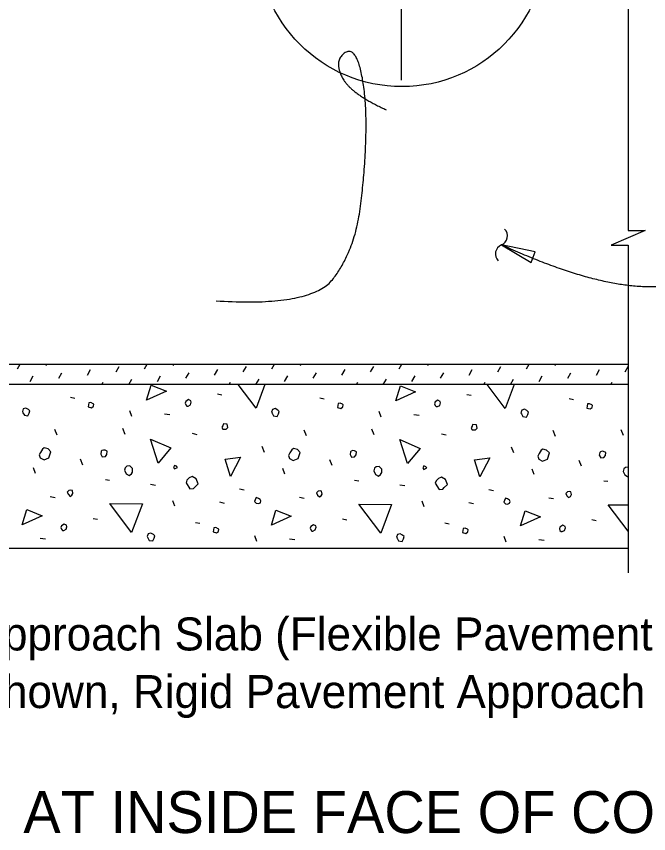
# Model space of a CAD drawing. Extents: x 110341.7 to 110413.5, y 110387.3 to 110417.8.
# Drawn here: x 110353.225 to 110357.09, y 110400.976 to 110405.967 of the extents above; entities that cross this region are included whole.
import ezdxf

# ---------------------------------------------------------------- set-up
doc = ezdxf.new("R2010")
doc.units = 0
for name, color, linetype in [('Border', 7, 'Continuous'), ('CL_Major', 7, 'Continuous'), ('Patterning', 7, 'Continuous'), ('PlotBorder_dp', 7, 'Continuous'), ('SheetBorder_dp', 7, 'Continuous')]:
    doc.layers.add(name, color=color, linetype=linetype)

msp = doc.modelspace()

# ---------------------------------------------------------------- linework, layer by layer
at = {"layer": 'Border'}
msp.add_lwpolyline([(110356.9647, 110406.5102), (110356.9647, 110404.6594), (110357.0681, 110404.6594), (110356.9647, 110404.6144), (110356.8614, 110404.5694), (110356.9647, 110404.5694), (110356.9647, 110402.5685)], dxfattribs=at)
msp.add_lwpolyline([(110356.1898, 110404.5723), (110356.3707, 110404.4632), (110356.3966, 110404.5289)], close=True, dxfattribs=at)
msp.add_circle((110355.5816, 110406.4215), 0.8833, dxfattribs=at)
for centre, start, end in [((110356.1667, 110404.6266), 292.7091, 44.4364), ((110356.2127, 110404.5166), 112.7091, 224.4364)]:
    msp.add_arc(centre, 0.0596, start, end, dxfattribs=at)
for points in [[(110354.4452, 110404.2301), (110355.0337, 110404.1926), (110355.2924, 110404.5405), (110355.3591, 110405.037), (110355.3654, 110405.4921), (110355.2924, 110405.7892), (110355.1649, 110405.6942), (110355.2675, 110405.4951), (110355.4853, 110405.3971)], [(110357.6069, 110404.3154), (110357.447, 110404.3154), (110356.7476, 110404.3154), (110356.1899, 110404.5723)]]:
    msp.add_open_spline(points, degree=2, dxfattribs=at)
at = {"layer": 'CL_Major'}
msp.add_line((110355.5778, 110414.9959), (110355.5778, 110405.5769), dxfattribs=at)
at = {"layer": 'Patterning'}
for p, q in [((110353.231, 110403.8158), (110353.2471, 110403.8435)), ((110353.406, 110403.8352), (110353.4109, 110403.8435)), ((110353.8338, 110403.7963), (110353.8533, 110403.8299)), ((110354.0089, 110403.8158), (110354.0249, 110403.8435)), ((110354.1839, 110403.8352), (110354.1887, 110403.8435)), ((110354.6117, 110403.7963), (110354.6311, 110403.8299)), ((110354.7867, 110403.8158), (110354.8027, 110403.8435)), ((110354.9617, 110403.8352), (110354.9665, 110403.8435)), ((110355.3895, 110403.7963), (110355.4089, 110403.8299)), ((110355.5645, 110403.8158), (110355.5806, 110403.8435)), ((110355.7395, 110403.8352), (110355.7443, 110403.8435)), ((110356.1673, 110403.7963), (110356.1867, 110403.8299)), ((110356.3423, 110403.8158), (110356.3584, 110403.8435)), ((110356.5173, 110403.8352), (110356.5221, 110403.8435)), ((110356.9451, 110403.7963), (110356.9646, 110403.8299)), ((110353.3088, 110403.738), (110353.3283, 110403.7716)), ((110353.4838, 110403.7574), (110353.5033, 110403.791)), ((110353.6588, 110403.7769), (110353.6783, 110403.8105)), ((110354.0866, 110403.738), (110354.1061, 110403.7716)), ((110354.2616, 110403.7574), (110354.2811, 110403.791)), ((110354.4367, 110403.7769), (110354.4561, 110403.8105)), ((110354.8645, 110403.738), (110354.8839, 110403.7716)), ((110355.0395, 110403.7574), (110355.0589, 110403.791)), ((110355.2145, 110403.7769), (110355.2339, 110403.8105)), ((110355.6423, 110403.738), (110355.6617, 110403.7716)), ((110355.8173, 110403.7574), (110355.8367, 110403.791)), ((110355.9923, 110403.7769), (110356.0117, 110403.8105)), ((110356.4201, 110403.738), (110356.4395, 110403.7716)), ((110356.5951, 110403.7574), (110356.6145, 110403.791)), ((110356.7701, 110403.7769), (110356.7896, 110403.8105)), ((110353.7479, 110403.7185), (110353.7561, 110403.7327)), ((110353.9116, 110403.7185), (110353.9311, 110403.7521)), ((110354.5257, 110403.7185), (110354.5339, 110403.7327)), ((110354.6894, 110403.7185), (110354.7089, 110403.7521)), ((110355.3035, 110403.7185), (110355.3117, 110403.7327)), ((110355.4673, 110403.7185), (110355.4867, 110403.7521)), ((110356.0813, 110403.7185), (110356.0895, 110403.7327)), ((110356.2451, 110403.7185), (110356.2645, 110403.7521)), ((110356.8591, 110403.7185), (110356.8673, 110403.7327)), ((110353.5565, 110403.6408), (110353.583, 110403.6355)), ((110354.4545, 110403.662), (110354.481, 110403.6567)), ((110355.0803, 110403.6372), (110355.1068, 110403.6319)), ((110355.9783, 110403.6584), (110356.0049, 110403.6531)), ((110356.6041, 110403.6337), (110356.6306, 110403.6284)), ((110353.9313, 110403.5241), (110353.9189, 110403.5577)), ((110354.131, 110403.54), (110354.1628, 110403.5365)), ((110355.4551, 110403.5206), (110355.4427, 110403.5541)), ((110355.6548, 110403.5365), (110355.6867, 110403.5329)), ((110353.4734, 110403.4092), (110353.4593, 110403.4445)), ((110353.8888, 110403.4145), (110353.8747, 110403.4498)), ((110354.299, 110403.4216), (110354.3272, 110403.4145)), ((110354.9972, 110403.4057), (110354.9831, 110403.441)), ((110355.4127, 110403.411), (110355.3985, 110403.4463)), ((110355.8228, 110403.418), (110355.8511, 110403.411)), ((110356.521, 110403.4021), (110356.5069, 110403.4375)), ((110356.9365, 110403.4074), (110356.9223, 110403.4428)), ((110354.7409, 110403.3049), (110354.7268, 110403.3402)), ((110356.2647, 110403.3014), (110356.2506, 110403.3367)), ((110353.6307, 110403.2271), (110353.6166, 110403.2625)), ((110355.1546, 110403.2236), (110355.1404, 110403.2589)), ((110356.6784, 110403.22), (110356.6642, 110403.2554)), ((110353.3426, 110403.1758), (110353.3302, 110403.2094)), ((110354.8664, 110403.1723), (110354.854, 110403.2059)), ((110356.3902, 110403.1688), (110356.3779, 110403.2024)), ((110353.7686, 110403.1387), (110353.7934, 110403.1352)), ((110355.2924, 110403.1352), (110355.3172, 110403.1317)), ((110356.8163, 110403.1317), (110356.841, 110403.1281)), ((110354.0444, 110403.1104), (110354.0745, 110403.1051)), ((110354.5889, 110403.0822), (110354.6172, 110403.0751)), ((110355.5682, 110403.1069), (110355.5983, 110403.1016)), ((110356.1127, 110403.0786), (110356.141, 110403.0715)), ((110353.431, 110403.0344), (110353.461, 110403.0291)), ((110354.9548, 110403.0309), (110354.9849, 110403.0256)), ((110356.4786, 110403.0274), (110356.5087, 110403.022)), ((110354.1929, 110402.9761), (110354.1805, 110403.0097)), ((110354.4669, 110403.0026), (110354.4952, 110402.9955)), ((110355.7167, 110402.9726), (110355.7043, 110403.0061)), ((110355.9907, 110402.9991), (110356.019, 110402.992)), ((110353.6944, 110402.9018), (110353.7209, 110402.8965)), ((110354.3202, 110402.8771), (110354.3467, 110402.8718)), ((110355.2182, 110402.8983), (110355.2447, 110402.893)), ((110355.844, 110402.8736), (110355.8705, 110402.8683)), ((110356.742, 110402.8948), (110356.7685, 110402.8895)), ((110353.3709, 110402.7799), (110353.4027, 110402.7763)), ((110354.6949, 110402.7604), (110354.6826, 110402.794)), ((110354.8947, 110402.7763), (110354.9265, 110402.7728)), ((110356.2188, 110402.7569), (110356.2064, 110402.7905)), ((110356.4185, 110402.7728), (110356.4503, 110402.7693))]:
    msp.add_line(p, q, dxfattribs=at)
for points in [[(110354.6896, 110403.5754), (110354.5808, 110403.7185)], [(110354.7432, 110403.7185), (110354.6896, 110403.5754)], [(110356.2135, 110403.5718), (110356.1019, 110403.7185)], [(110356.2683, 110403.7185), (110356.2135, 110403.5718)], [(110354.0197, 110403.6231), (110354.0479, 110403.715), (110354.1416, 110403.6779), (110354.0197, 110403.6231)], [(110355.5435, 110403.6196), (110355.5718, 110403.7115), (110355.6654, 110403.6744), (110355.5435, 110403.6196)], [(110354.2671, 110403.5877), (110354.2742, 110403.5877), (110354.2884, 110403.5948), (110354.2937, 110403.6107), (110354.2919, 110403.6196), (110354.2778, 110403.6266), (110354.2601, 110403.616), (110354.2565, 110403.6054), (110354.2601, 110403.5948), (110354.2671, 110403.5877)], [(110355.791, 110403.5842), (110355.798, 110403.5842), (110355.8122, 110403.5913), (110355.8175, 110403.6072), (110355.8157, 110403.616), (110355.8016, 110403.6231), (110355.7839, 110403.6125), (110355.7804, 110403.6019), (110355.7839, 110403.5913), (110355.791, 110403.5842)], [(110353.2648, 110403.5471), (110353.2737, 110403.5312), (110353.2949, 110403.5276), (110353.3037, 110403.5435), (110353.3072, 110403.5577), (110353.2984, 110403.5665), (110353.2825, 110403.5754), (110353.2666, 110403.5701), (110353.2613, 110403.5541), (110353.2648, 110403.5471)], [(110353.6643, 110403.5824), (110353.6838, 110403.5771), (110353.6962, 110403.586), (110353.6979, 110403.5983), (110353.6944, 110403.6019), (110353.6802, 110403.6089), (110353.6679, 110403.6072), (110353.6661, 110403.5948), (110353.6643, 110403.5824)], [(110354.7886, 110403.5435), (110354.7975, 110403.5276), (110354.8187, 110403.5241), (110354.8275, 110403.54), (110354.8311, 110403.5541), (110354.8222, 110403.563), (110354.8063, 110403.5718), (110354.7904, 110403.5665), (110354.7851, 110403.5506), (110354.7886, 110403.5435)], [(110355.1882, 110403.5789), (110355.2076, 110403.5736), (110355.22, 110403.5824), (110355.2217, 110403.5948), (110355.2182, 110403.5983), (110355.2041, 110403.6054), (110355.1917, 110403.6036), (110355.1899, 110403.5913), (110355.1882, 110403.5789)], [(110356.3124, 110403.54), (110356.3213, 110403.5241), (110356.3425, 110403.5206), (110356.3513, 110403.5365), (110356.3549, 110403.5506), (110356.346, 110403.5594), (110356.3301, 110403.5683), (110356.3142, 110403.563), (110356.3089, 110403.5471), (110356.3124, 110403.54)], [(110356.712, 110403.5754), (110356.7314, 110403.5701), (110356.7438, 110403.5789), (110356.7456, 110403.5913), (110356.742, 110403.5948), (110356.7279, 110403.6019), (110356.7155, 110403.6001), (110356.7137, 110403.5877), (110356.712, 110403.5754)], [(110354.4863, 110403.4463), (110354.5076, 110403.4463), (110354.5182, 110403.4569), (110354.5129, 110403.4764), (110354.4899, 110403.4781), (110354.4863, 110403.4675), (110354.481, 110403.4587), (110354.4863, 110403.4463), (110354.4828, 110403.4498)], [(110356.0102, 110403.4428), (110356.0314, 110403.4428), (110356.042, 110403.4534), (110356.0367, 110403.4728), (110356.0137, 110403.4746), (110356.0102, 110403.464), (110356.0049, 110403.4552), (110356.0102, 110403.4428), (110356.0066, 110403.4463)], [(110354.0921, 110403.2395), (110354.0444, 110403.3862), (110354.1699, 110403.3314), (110354.0921, 110403.2395)], [(110355.6159, 110403.2359), (110355.5682, 110403.3827), (110355.6937, 110403.3279), (110355.6159, 110403.2359)], [(110353.3709, 110403.2713), (110353.3939, 110403.2589), (110353.4239, 110403.2713), (110353.4363, 110403.3084), (110353.4186, 110403.3261), (110353.3956, 110403.3314), (110353.385, 110403.3243), (110353.3727, 110403.3049), (110353.3638, 110403.289), (110353.3709, 110403.2713)], [(110353.7403, 110403.2943), (110353.7492, 110403.2784), (110353.7686, 110403.2801), (110353.7775, 110403.2925), (110353.7792, 110403.312), (110353.7669, 110403.3173), (110353.758, 110403.319), (110353.7474, 110403.3155), (110353.7439, 110403.312), (110353.7403, 110403.2943)], [(110354.8947, 110403.2678), (110354.9177, 110403.2554), (110354.9477, 110403.2678), (110354.9601, 110403.3049), (110354.9424, 110403.3226), (110354.9194, 110403.3279), (110354.9088, 110403.3208), (110354.8965, 110403.3014), (110354.8876, 110403.2854), (110354.8947, 110403.2678)], [(110356.4185, 110403.2642), (110356.4415, 110403.2519), (110356.4715, 110403.2642), (110356.4839, 110403.3014), (110356.4662, 110403.319), (110356.4433, 110403.3243), (110356.4327, 110403.3173), (110356.4203, 110403.2978), (110356.4114, 110403.2819), (110356.4185, 110403.2642)], [(110354.5341, 110403.1582), (110354.5005, 110403.2625), (110354.5942, 110403.2748), (110354.5341, 110403.1582)], [(110355.2642, 110403.2907), (110355.273, 110403.2748), (110355.2924, 110403.2766), (110355.3013, 110403.289), (110355.3031, 110403.3084), (110355.2907, 110403.3137), (110355.2818, 110403.3155), (110355.2712, 110403.312), (110355.2677, 110403.3084), (110355.2642, 110403.2907)], [(110356.0579, 110403.1546), (110356.0243, 110403.2589), (110356.118, 110403.2713), (110356.0579, 110403.1546)], [(110356.788, 110403.2872), (110356.7968, 110403.2713), (110356.8163, 110403.2731), (110356.8251, 110403.2854), (110356.8269, 110403.3049), (110356.8145, 110403.3102), (110356.8057, 110403.312), (110356.7951, 110403.3084), (110356.7915, 110403.3049), (110356.788, 110403.2872)], [(110353.8853, 110403.1953), (110353.8959, 110403.1741), (110353.9136, 110403.1635), (110353.9277, 110403.1741), (110353.9348, 110403.1847), (110353.9348, 110403.2059), (110353.9189, 110403.2218), (110353.8994, 110403.22), (110353.8906, 110403.2112), (110353.8853, 110403.1953)], [(110354.1911, 110403.2041), (110354.2106, 110403.213), (110354.2035, 110403.22), (110354.1911, 110403.2253), (110354.1858, 110403.213), (110354.1911, 110403.2041)], [(110355.4091, 110403.1918), (110355.4197, 110403.1705), (110355.4374, 110403.1599), (110355.4515, 110403.1705), (110355.4586, 110403.1811), (110355.4586, 110403.2024), (110355.4427, 110403.2183), (110355.4233, 110403.2165), (110355.4144, 110403.2077), (110355.4091, 110403.1918)], [(110355.7149, 110403.2006), (110355.7344, 110403.2094), (110355.7273, 110403.2165), (110355.7149, 110403.2218), (110355.7096, 110403.2094), (110355.7149, 110403.2006)], [(110356.9648, 110403.2146), (110356.9471, 110403.213), (110356.9382, 110403.2041), (110356.9329, 110403.1882)], [(110356.9329, 110403.1882), (110356.9435, 110403.167), (110356.9612, 110403.1564), (110356.9648, 110403.1591)], [(110354.2618, 110403.1193), (110354.2848, 110403.0822), (110354.3078, 110403.0839), (110354.3166, 110403.0928), (110354.3361, 110403.1122), (110354.3237, 110403.1423), (110354.299, 110403.1564), (110354.2813, 110403.1493), (110354.2671, 110403.1352), (110354.2618, 110403.1193)], [(110355.7857, 110403.1157), (110355.8086, 110403.0786), (110355.8316, 110403.0804), (110355.8405, 110403.0892), (110355.8599, 110403.1087), (110355.8475, 110403.1387), (110355.8228, 110403.1529), (110355.8051, 110403.1458), (110355.791, 110403.1317), (110355.7857, 110403.1157)], [(110353.5424, 110403.0468), (110353.553, 110403.0362), (110353.5636, 110403.0433), (110353.5706, 110403.0539), (110353.5671, 110403.0715), (110353.5583, 110403.0733), (110353.5459, 110403.0715), (110353.5353, 110403.0609), (110353.5424, 110403.0468)], [(110355.0662, 110403.0433), (110355.0768, 110403.0327), (110355.0874, 110403.0397), (110355.0945, 110403.0503), (110355.0909, 110403.068), (110355.0821, 110403.0698), (110355.0697, 110403.068), (110355.0591, 110403.0574), (110355.0662, 110403.0433)], [(110354.6914, 110402.9938), (110354.7038, 110402.992), (110354.7162, 110402.9973), (110354.7197, 110403.0079), (110354.7144, 110403.0167), (110354.7038, 110403.0238), (110354.6914, 110403.0291), (110354.6843, 110403.015), (110354.6808, 110403.0044), (110354.6914, 110402.9938)], [(110356.2152, 110402.9902), (110356.2276, 110402.9885), (110356.24, 110402.9938), (110356.2435, 110403.0044), (110356.2382, 110403.0132), (110356.2276, 110403.0203), (110356.2152, 110403.0256), (110356.2082, 110403.0114), (110356.2046, 110403.0008), (110356.2152, 110402.9902)], [(110356.59, 110403.0397), (110356.6006, 110403.0291), (110356.6112, 110403.0362), (110356.6183, 110403.0468), (110356.6147, 110403.0645), (110356.6059, 110403.0662), (110356.5935, 110403.0645), (110356.5829, 110403.0539), (110356.59, 110403.0397)], [(110353.9295, 110402.8152), (110353.7951, 110402.992), (110353.9949, 110402.9902), (110353.9295, 110402.8152)], [(110355.4533, 110402.8117), (110355.319, 110402.9885), (110355.5187, 110402.9867), (110355.4533, 110402.8117)], [(110356.9648, 110402.8244), (110356.8428, 110402.9849), (110356.9648, 110402.9838)], [(110353.2595, 110402.8629), (110353.2878, 110402.9549), (110353.3815, 110402.9178), (110353.2595, 110402.8629)], [(110354.7833, 110402.8594), (110354.8116, 110402.9513), (110354.9053, 110402.9142), (110354.7833, 110402.8594)], [(110356.3071, 110402.8559), (110356.3354, 110402.9478), (110356.4291, 110402.9107), (110356.3071, 110402.8559)], [(110353.507, 110402.8276), (110353.5141, 110402.8276), (110353.5282, 110402.8347), (110353.5335, 110402.8506), (110353.5318, 110402.8594), (110353.5176, 110402.8665), (110353.4999, 110402.8559), (110353.4964, 110402.8453), (110353.4999, 110402.8347), (110353.507, 110402.8276)], [(110354.428, 110402.8188), (110354.4475, 110402.8135), (110354.4598, 110402.8223), (110354.4616, 110402.8347), (110354.4581, 110402.8382), (110354.4439, 110402.8453), (110354.4315, 110402.8435), (110354.4298, 110402.8311), (110354.428, 110402.8188)], [(110355.0308, 110402.8241), (110355.0379, 110402.8241), (110355.052, 110402.8311), (110355.0573, 110402.847), (110355.0556, 110402.8559), (110355.0414, 110402.8629), (110355.0237, 110402.8523), (110355.0202, 110402.8417), (110355.0237, 110402.8311), (110355.0308, 110402.8241)], [(110355.9518, 110402.8152), (110355.9713, 110402.8099), (110355.9836, 110402.8188), (110355.9854, 110402.8311), (110355.9819, 110402.8347), (110355.9677, 110402.8417), (110355.9554, 110402.84), (110355.9536, 110402.8276), (110355.9518, 110402.8152)], [(110356.5546, 110402.8205), (110356.5617, 110402.8205), (110356.5758, 110402.8276), (110356.5812, 110402.8435), (110356.5794, 110402.8523), (110356.5652, 110402.8594), (110356.5476, 110402.8488), (110356.544, 110402.8382), (110356.5476, 110402.8276), (110356.5546, 110402.8205)], [(110354.0285, 110402.7834), (110354.0373, 110402.7675), (110354.0585, 110402.764), (110354.0674, 110402.7799), (110354.0709, 110402.794), (110354.0621, 110402.8028), (110354.0462, 110402.8117), (110354.0303, 110402.8064), (110354.025, 110402.7905), (110354.0285, 110402.7834)], [(110355.5523, 110402.7799), (110355.5611, 110402.764), (110355.5824, 110402.7604), (110355.5912, 110402.7763), (110355.5947, 110402.7905), (110355.5859, 110402.7993), (110355.57, 110402.8081), (110355.5541, 110402.8028), (110355.5488, 110402.7869), (110355.5523, 110402.7799)]]:
    msp.add_lwpolyline(points, dxfattribs=at)
at = {"layer": 'PlotBorder_dp'}
for p, q in [((110344.5778, 110403.8435), (110356.9648, 110403.8435)), ((110356.9648, 110403.7185), (110344.5778, 110403.7185)), ((110356.9648, 110402.7185), (110344.5778, 110402.7185))]:
    msp.add_line(p, q, dxfattribs=at)

# ---------------------------------------------------------------- texts
at = {"layer": 'Border'}
for s, p in [('Approach Slab (Flexible Pavement Approach Slab ', (110352.9629, 110402.095)), ('Shown, Rigid Pavement Approach Slab Similar)', (110352.9629, 110401.743))]:
    msp.add_text(s, height=0.2016, dxfattribs=at).set_placement(p)
at = {"layer": 'SheetBorder_dp'}
msp.add_text('ELEVATION AT INSIDE FACE OF CONCRETE PARAPET', height=0.256001, dxfattribs=at).set_placement((110351.2508, 110400.9799))

doc.saveas('drawing.dxf')
